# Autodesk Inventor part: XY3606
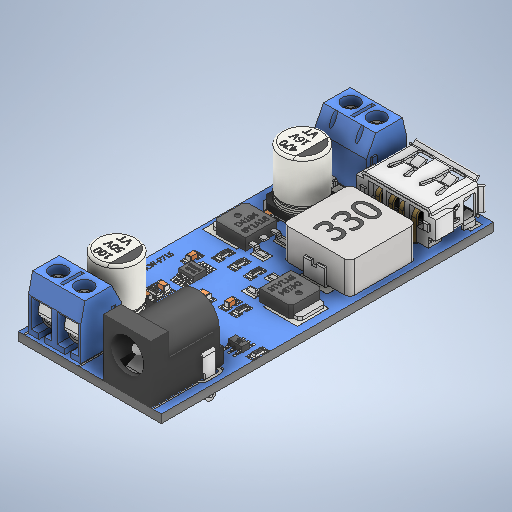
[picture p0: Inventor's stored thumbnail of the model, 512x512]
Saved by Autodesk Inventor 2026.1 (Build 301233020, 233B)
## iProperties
Created: 2026-08
Part Number: XY3606
Material: Generic
Document SubType Name: Modeling
Designer: hp
Density: 1 g/cm^3
Appearance: Default
Title: XY3606.stp
Author: quang
Sending System: Autodesk Inventor 2024
Preprocessor: ST-DEVELOPER v20
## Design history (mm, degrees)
feature "Solid1"
body "Solid2"
